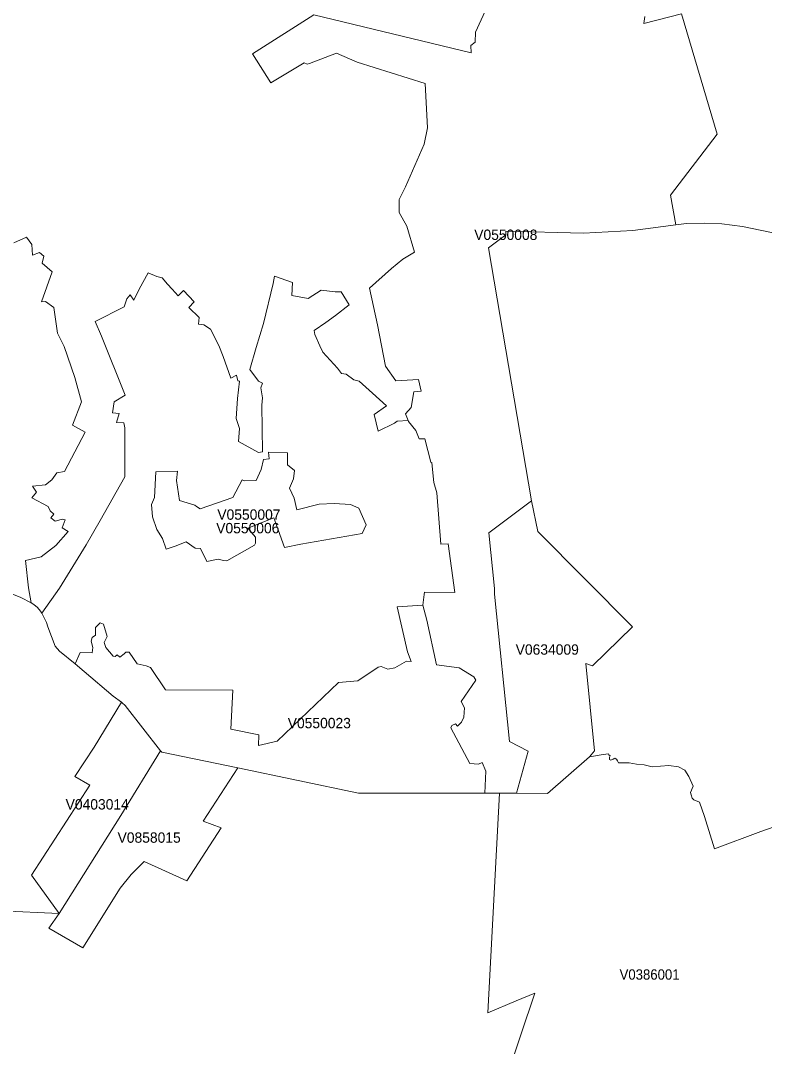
# Model space of a CAD drawing. Extents: x 369010 to 735936, y 6377141 to 6616555.
# Drawn here: x 433279 to 440462, y 6480546 to 6490450 of the extents above; entities that cross this region are included whole.
import ezdxf
from ezdxf.enums import TextEntityAlignment as Align

# ---------------------------------------------------------------- set-up
doc = ezdxf.new("R2010")
doc.units = 0
doc.header["$LTSCALE"] = 40
doc.layers.add('3', color=7, linetype='Continuous', lineweight=13)
doc.layers.add('4', color=7, linetype='Continuous')

msp = doc.modelspace()

# ---------------------------------------------------------------- linework, layer by layer
at = {"layer": '3'}
for points in [[(437780.59, 6490576.1), (437671.19, 6490336.45), (437667.22, 6490241.45), (437627.17, 6490208.52), (437631.14, 6490138.84), (436110.33, 6490505.93), (435519.31, 6490129.24), (435695.24, 6489847.06), (436018.97, 6490041.53), (436044.79, 6490029.28), (436069.94, 6490035.07), (436328.63, 6490133.05), (436530.21, 6490047.98), (437184.94, 6489841.43), (437207.95, 6489413.6), (437176.01, 6489256.87), (436994.78, 6488844.27), (436934.7, 6488720.8), (436933.54, 6488596.84), (437009.01, 6488465.27), (437082.5, 6488214.36), (436970.62, 6488144.68), (436859.07, 6488055.64), (436648.88, 6487866.31), (436726.33, 6487510.8), (436801.31, 6487112.11), (436901.77, 6486971.59), (437121.72, 6486985.16), (437148.04, 6486870.3), (437075.21, 6486863.85), (437049.56, 6486714.4), (436997.26, 6486653.66), (437022.09, 6486587.29), (437024.9, 6486579.51), (437095.74, 6486491.13), (437126.69, 6486411.86), (437181.47, 6486410.53), (437239.56, 6486184.95), (437250.48, 6486181.15), (437270.84, 6485991.15), (437297.98, 6485891.84), (437336.71, 6485394.34), (437409.04, 6485398.81), (437471.6, 6484929.27), (437180.64, 6484932.75), (437177.33, 6484908.75), (437162.93, 6484804.65), (437201.99, 6484662.48), (437294.84, 6484229.69), (437515.12, 6484200.56), (437655.47, 6484113.5), (437675.17, 6484080.24), (437534.82, 6483875.18), (437566.43, 6483813.28), (437557.99, 6483724.57), (437535.81, 6483675.75), (437498.74, 6483637.02), (437477.22, 6483661.18), (437444.62, 6483643.64), (437432.21, 6483620.14), (437617.74, 6483278.87), (437701.32, 6483271.09), (437736.73, 6483288.3), (437770, 6483202.9), (437760.4, 6482990.89), (437904.72, 6482990.72), (438066.75, 6482989.9), (438180.12, 6483395.88), (438001.21, 6483488.4), (437855.24, 6484912.56), (437855.24, 6484968.17), (437800.29, 6485502.91), (438213.22, 6485811.91), (437795.82, 6488254.74), (437964.3, 6488381.52), (437963.47, 6488414.95), (438713.7, 6488397.41), (439190.19, 6488422.9), (439607.1, 6488477.84), (439553.64, 6488763.34), (440006.29, 6489352.37), (439660.88, 6490514.87), (439298.43, 6490421.36), (439305.55, 6490489.05)], [(437022.09, 6486587.29), (436997.26, 6486653.66), (437049.56, 6486714.4), (437075.21, 6486863.85), (437148.04, 6486870.3), (437121.72, 6486985.16), (436901.77, 6486971.59), (436801.31, 6487112.11), (436726.33, 6487510.8), (436648.88, 6487866.31), (436859.07, 6488055.64), (436970.62, 6488144.68), (437082.5, 6488214.36), (437009.01, 6488465.27), (436933.54, 6488596.84), (436934.7, 6488720.8), (436994.78, 6488844.27), (437176.01, 6489256.87), (437207.95, 6489413.6), (437184.94, 6489841.43), (436530.21, 6490047.98), (436328.63, 6490133.05), (436069.94, 6490035.07), (436044.79, 6490029.28), (436018.97, 6490041.53), (435695.24, 6489847.06), (435519.31, 6490129.24), (436110.33, 6490505.93)], [(436110.33, 6490505.93), (437631.14, 6490138.84), (437627.17, 6490208.52), (437667.22, 6490241.45), (437671.19, 6490336.45), (437780.59, 6490576.1)], [(439305.55, 6490489.05), (439298.43, 6490421.36), (439660.88, 6490514.87), (440006.29, 6489352.37)], [(440006.29, 6489352.37), (439553.64, 6488763.34), (439607.1, 6488477.84), (439707.72, 6488491.25), (439879.51, 6488494.06), (440049.65, 6488488.6), (440248.92, 6488462.62), (440962.9, 6488312.51)], [(440962.9, 6488312.51), (440248.92, 6488462.62), (440049.65, 6488488.6), (439879.51, 6488494.06), (439707.72, 6488491.25), (439607.1, 6488477.84), (439190.19, 6488422.9), (438713.7, 6488397.41), (437963.47, 6488414.95), (437964.3, 6488381.52), (437795.82, 6488254.74), (438213.22, 6485811.91), (438273.3, 6485518.47), (439187.05, 6484598.1), (438802.25, 6484219.26), (438736.21, 6484243.26), (438820.29, 6483401.17), (438770.8, 6483343.25), (438905.85, 6483363.44), (438955.84, 6483369.89), (438959.64, 6483360.13), (438971.39, 6483352.68), (438966.1, 6483337.12), (438966.59, 6483315.61), (438977.85, 6483310.31), (438999.86, 6483319.42), (439015.42, 6483327.53), (439026.18, 6483322.56), (439034.29, 6483318.26), (439041.24, 6483301.71), (439050.84, 6483284.49), (439154.44, 6483285.16), (439227.43, 6483272.08), (439299.59, 6483264.47), (439377.38, 6483246.43), (439539.57, 6483258.51), (439633.24, 6483244.44), (439692.5, 6483211.67), (439732.38, 6483150.77), (439772.6, 6483059.08), (439746.95, 6482996.52), (439754.56, 6482973.35), (439764.82, 6482942.4), (439778.56, 6482927.83), (439833.5, 6482903.83), (439882.16, 6482766.3), (439978.98, 6482454.66), (440425.02, 6482620.16), (440885.78, 6482782.52)], [(433162.2, 6484926.96), (433280.21, 6484879.13), (433381, 6484828.98), (433357, 6484973.96), (433325.56, 6485237.11), (433477.32, 6485272.86), (433620.82, 6485380.93), (433737.33, 6485517.47), (433681.56, 6485553.72), (433709.53, 6485630.35), (433682.88, 6485635.48), (433669.97, 6485633), (433614.2, 6485615.45), (433570.67, 6485649.88), (433598.97, 6485685.46), (433563.88, 6485715.91), (433546.34, 6485756.79), (433386.96, 6485841.7), (433432.14, 6485897.97), (433393.08, 6485953.74), (433520.35, 6485966.65), (433582.58, 6486016.3), (433630.58, 6486082.5), (433703.24, 6486094.75), (433904.16, 6486475.25), (433780.03, 6486543.6), (433866.75, 6486769.51), (433801.71, 6487003.7), (433698.93, 6487302.27), (433636.04, 6487432.69), (433599.13, 6487680.11), (433521.35, 6487737.54), (433480.47, 6487735.06), (433583.91, 6488024.03), (433486.92, 6488106.12), (433505.13, 6488173.48), (433463.59, 6488210.56), (433393.41, 6488183.58), (433386.46, 6488288.84), (433337.8, 6488359.51), (433215, 6488302.91)], [(433215, 6488302.91), (433337.8, 6488359.51), (433386.46, 6488288.84), (433393.41, 6488183.58), (433463.59, 6488210.56), (433505.13, 6488173.48), (433486.92, 6488106.12), (433583.91, 6488024.03), (433480.47, 6487735.06), (433521.35, 6487737.54), (433599.13, 6487680.11), (433636.04, 6487432.69), (433698.93, 6487302.27), (433801.71, 6487003.7), (433866.75, 6486769.51), (433780.03, 6486543.6), (433904.16, 6486475.25), (433703.24, 6486094.75), (433630.58, 6486082.5), (433582.58, 6486016.3), (433520.35, 6485966.65), (433393.08, 6485953.74), (433432.14, 6485897.97)], [(433432.14, 6485897.97), (433386.96, 6485841.7), (433546.34, 6485756.79), (433563.88, 6485715.91), (433598.97, 6485685.46), (433570.67, 6485649.88), (433614.2, 6485615.45), (433669.97, 6485633), (433682.88, 6485635.48), (433709.53, 6485630.35), (433681.56, 6485553.72), (433737.33, 6485517.47), (433620.82, 6485380.93), (433477.32, 6485272.86), (433325.56, 6485237.11), (433357, 6484973.96), (433381, 6484828.98), (433382.32, 6484828.32), (433408.31, 6484812.1), (433442.4, 6484782.14), (433473.02, 6484747.38), (433482.95, 6484727.52), (433655.24, 6484968.83), (433911.44, 6485388.55), (434049.31, 6485624.72), (434287.3, 6486044.27), (434284.32, 6486517.78), (434276.54, 6486566.44), (434207.03, 6486567.76), (434231.86, 6486654.65), (434166.98, 6486661.77), (434183.36, 6486768.68), (434290.61, 6486832.57), (434061.06, 6487403.89), (434000.81, 6487543.41), (434279.02, 6487684.75), (434305.51, 6487762.7), (434338.11, 6487800.27), (434372.87, 6487748.8), (434425.83, 6487857.2), (434511.72, 6488012.78), (434594.31, 6487979.18), (434647.11, 6487966.6), (434696.76, 6487905.37), (434744.42, 6487855.71), (434801.19, 6487792.99), (434851.5, 6487844.46), (434954.61, 6487732.58), (434902.97, 6487677.8), (435004.76, 6487584.29), (434997.64, 6487517.92), (435048.62, 6487512.13), (435111.84, 6487469.59), (435194.1, 6487313.36), (435235.97, 6487204.95), (435308.79, 6486997.58), (435364.73, 6487024.88), (435375.65, 6486970.76), (435394.36, 6486966.79), (435373.83, 6486801.62), (435359.44, 6486606.66), (435394.36, 6486510.66), (435383.93, 6486384.71), (435577.24, 6486280.94), (435614.64, 6486284.92), (435609.18, 6486736.91), (435614.31, 6486807.58), (435598.26, 6486902.41), (435614.31, 6486947.59), (435577.07, 6486967.29), (435493.33, 6487079.5), (435554.07, 6487293.66), (435624.24, 6487524.04), (435718.91, 6487911.16), (435731.82, 6487980.84), (435906.26, 6487919.43), (435897.82, 6487796.13), (436056.54, 6487767.83), (436180, 6487846.12), (436318.2, 6487831.72), (436374.47, 6487829.73), (436450.6, 6487705.93), (436320.85, 6487602.66), (436227.83, 6487534.97), (436112.81, 6487458.67), (436119.93, 6487418.78), (436168.92, 6487309.05), (436197.22, 6487248.31), (436340.21, 6487092.58), (436376.95, 6487040.94), (436422.8, 6487036.47), (436497.44, 6486982.68), (436547.09, 6486969.77), (436676.68, 6486853.92), (436813.88, 6486729.96), (436693.56, 6486646.21), (436731.96, 6486485.67), (436888.03, 6486561.64), (436915.83, 6486582.33), (437022.09, 6486587.29)], [(435394.36, 6486966.79), (435375.65, 6486970.76), (435364.73, 6487024.88), (435308.79, 6486997.58), (435235.97, 6487204.95), (435194.1, 6487313.36), (435111.84, 6487469.59), (435048.62, 6487512.13), (434997.64, 6487517.92), (435004.76, 6487584.29), (434902.97, 6487677.8), (434954.61, 6487732.58), (434851.5, 6487844.46), (434801.19, 6487792.99), (434744.42, 6487855.71), (434696.76, 6487905.37), (434647.11, 6487966.6), (434594.31, 6487979.18), (434511.72, 6488012.78), (434425.83, 6487857.2), (434372.87, 6487748.8), (434338.11, 6487800.27), (434305.51, 6487762.7), (434279.02, 6487684.75), (434000.81, 6487543.41), (434061.06, 6487403.89), (434290.61, 6486832.57), (434183.36, 6486768.68), (434166.98, 6486661.77), (434231.86, 6486654.65), (434207.03, 6486567.76), (434276.54, 6486566.44), (434284.32, 6486517.78), (434287.3, 6486044.27), (434049.31, 6485624.72), (433911.44, 6485388.55), (433655.24, 6484968.83), (433482.95, 6484727.52)], [(433482.95, 6484727.52), (433528.13, 6484637.49), (433542.86, 6484595.78), (433612.71, 6484411.08), (433656.23, 6484362.26), (433805.85, 6484238.13), (433854.84, 6484349.84), (433971.85, 6484346.37), (433975.82, 6484397.84), (433962.08, 6484457.92), (433971.85, 6484492.51), (434001.81, 6484514.69), (434003.79, 6484591.64), (434048.81, 6484634.01), (434079.92, 6484622.43), (434115.67, 6484503.1), (434087.7, 6484445.67), (434101.94, 6484396.02), (434173.1, 6484314.43), (434191.97, 6484309.29), (434213.49, 6484326.01), (434236.82, 6484303.17), (434278.03, 6484337.1), (434295.24, 6484350.67), (434326.52, 6484350.67), (434404.81, 6484240.94), (434493.19, 6484221.41), (434532.41, 6484203.7), (434678.88, 6483989.21), (435329.81, 6483985.9), (435308.29, 6483607.72), (435580.22, 6483553.6), (435576.41, 6483451.16), (435755.49, 6483493.03), (436347.66, 6484058.89), (436535.01, 6484074.61), (436730.64, 6484206.35), (436761.25, 6484214.13), (436825.3, 6484189.3), (436892.66, 6484200.89), (437004.21, 6484264.61), (437051.22, 6484262.62), (437014.64, 6484356.63), (436915.17, 6484790.58), (437162.93, 6484804.65), (437177.33, 6484908.75), (437180.64, 6484932.75), (437471.6, 6484929.27), (437409.04, 6485398.81), (437336.71, 6485394.34), (437297.98, 6485891.84), (437270.84, 6485991.15), (437250.48, 6486181.15), (437239.56, 6486184.95), (437181.47, 6486410.53), (437126.69, 6486411.86), (437095.74, 6486491.13), (437024.9, 6486579.51), (437022.09, 6486587.29), (436915.83, 6486582.33), (436888.03, 6486561.64), (436731.96, 6486485.67), (436693.56, 6486646.21), (436813.88, 6486729.96), (436676.68, 6486853.92), (436547.09, 6486969.77), (436497.44, 6486982.68), (436422.8, 6487036.47), (436376.95, 6487040.94), (436340.21, 6487092.58), (436197.22, 6487248.31), (436168.92, 6487309.05), (436119.93, 6487418.78), (436112.81, 6487458.67), (436227.83, 6487534.97), (436320.85, 6487602.66), (436450.6, 6487705.93), (436374.47, 6487829.73), (436318.2, 6487831.72), (436180, 6487846.12), (436056.54, 6487767.83), (435897.82, 6487796.13), (435906.26, 6487919.43), (435731.82, 6487980.84), (435718.91, 6487911.16), (435624.24, 6487524.04), (435554.07, 6487293.66), (435493.33, 6487079.5), (435577.07, 6486967.29), (435614.31, 6486947.59), (435598.26, 6486902.41), (435614.31, 6486807.58), (435609.18, 6486736.91), (435614.64, 6486284.92), (435577.24, 6486280.94), (435383.93, 6486384.71), (435394.36, 6486510.66), (435359.44, 6486606.66), (435373.83, 6486801.62), (435394.36, 6486966.79)], [(433088.22, 6481856.03), (433652.59, 6481829.22), (433384.64, 6482198.62), (433947.52, 6483068.84), (433803.86, 6483152.42), (433990.05, 6483434.94), (434254.53, 6483868.23), (434172.94, 6483926.65), (433891.75, 6484166.8), (433805.85, 6484238.13), (433656.23, 6484362.26), (433612.71, 6484411.08), (433542.86, 6484595.78), (433528.13, 6484637.49), (433482.95, 6484727.52), (433473.02, 6484747.38), (433442.4, 6484782.14), (433408.31, 6484812.1), (433382.32, 6484828.32), (433381, 6484828.98), (433280.21, 6484879.13), (433162.2, 6484926.96)], [(440885.78, 6482782.52), (440425.02, 6482620.16), (439978.98, 6482454.66), (439882.16, 6482766.3), (439833.5, 6482903.83), (439778.56, 6482927.83), (439764.82, 6482942.4), (439754.56, 6482973.35), (439746.95, 6482996.52), (439772.6, 6483059.08), (439732.38, 6483150.77), (439692.5, 6483211.67), (439633.24, 6483244.44), (439539.57, 6483258.51), (439377.38, 6483246.43), (439299.59, 6483264.47), (439227.43, 6483272.08), (439154.44, 6483285.16), (439050.84, 6483284.49), (439041.24, 6483301.71), (439034.29, 6483318.26), (439026.18, 6483322.56), (439015.42, 6483327.53), (438999.86, 6483319.42), (438977.85, 6483310.31), (438966.59, 6483315.61), (438966.1, 6483337.12), (438971.39, 6483352.68), (438959.64, 6483360.13), (438955.84, 6483369.89), (438905.85, 6483363.44), (438770.8, 6483343.25), (438365.65, 6482989.23), (438066.75, 6482989.9), (437904.72, 6482990.72), (437791.52, 6480871.28), (438064.43, 6480985.15), (438244, 6481059.13), (437970.43, 6480244.85)], [(435376.15, 6483235.17), (435040.84, 6482720.46), (435215.61, 6482656.41), (434885.76, 6482145.66), (434473.33, 6482330.53), (434346.55, 6482204.25), (434240.96, 6482074.83), (433881.32, 6481498.37), (433550.97, 6481687.71), (433652.59, 6481829.22), (433088.22, 6481856.03)], [(437970.43, 6480244.85), (438244, 6481059.13), (438064.43, 6480985.15), (437791.52, 6480871.28), (437904.72, 6482990.72), (437760.4, 6482990.89), (436541.3, 6482992.21), (435376.15, 6483235.17)]]:
    msp.add_lwpolyline(points, dxfattribs=at)
for points in [[(434795.4, 6486100.05), (434586.37, 6486092.6), (434573.46, 6485843.68), (434544.16, 6485777.81), (434553.76, 6485660.14), (434593.81, 6485536.51), (434650.75, 6485450.44), (434684.34, 6485347), (434772.89, 6485375.8), (434879.64, 6485418.01), (434965.37, 6485357.43), (435015.85, 6485353.46), (435076.75, 6485225.86), (435188.63, 6485249.85), (435239.61, 6485236.28), (435269.24, 6485232.48), (435538.01, 6485384.41), (435548.77, 6485405.1), (435547.45, 6485463.19), (435473.3, 6485549.58), (435724.04, 6485648.06), (435735.13, 6485623.56), (435827.81, 6485363.39), (435983.72, 6485394.01), (436577.88, 6485496.79), (436616.6, 6485579.87), (436545.77, 6485741.73), (436463.35, 6485779.14), (436308.43, 6485787.91), (436160.64, 6485780.46), (435946.97, 6485725.18), (435920.82, 6485839.54), (435876.8, 6485934.38), (435913.54, 6486026.56), (435925.13, 6486105.18), (435857.27, 6486160.29), (435856.61, 6486218.88), (435857.93, 6486274.99), (435673.73, 6486281.61), (435679.52, 6486220.04), (435624.74, 6486211.6), (435602.06, 6486116.27), (435552.74, 6486009.68), (435439.7, 6486005.21), (435419.84, 6486014.15), (435329.48, 6485846), (435012.37, 6485735.61), (434976.29, 6485756.79), (434961.4, 6485770.36), (434814.26, 6485816.87), (434785.14, 6486009.19)], [(434795.4, 6486100.05), (434785.14, 6486009.19), (434814.26, 6485816.87), (434961.4, 6485770.36), (434976.29, 6485756.79), (435012.37, 6485735.61), (435329.48, 6485846), (435419.84, 6486014.15), (435439.7, 6486005.21), (435552.74, 6486009.68), (435602.06, 6486116.27), (435624.74, 6486211.6), (435679.52, 6486220.04), (435673.73, 6486281.61), (435857.93, 6486274.99), (435856.61, 6486218.88), (435857.27, 6486160.29), (435925.13, 6486105.18), (435913.54, 6486026.56), (435876.8, 6485934.38), (435920.82, 6485839.54), (435946.97, 6485725.18), (436160.64, 6485780.46), (436308.43, 6485787.91), (436463.35, 6485779.14), (436545.77, 6485741.73), (436616.6, 6485579.87), (436577.88, 6485496.79), (435983.72, 6485394.01), (435827.81, 6485363.39), (435735.13, 6485623.56), (435724.04, 6485648.06), (435473.3, 6485549.58), (435547.45, 6485463.19), (435548.77, 6485405.1), (435538.01, 6485384.41), (435269.24, 6485232.48), (435239.61, 6485236.28), (435188.63, 6485249.85), (435076.75, 6485225.86), (435015.85, 6485353.46), (434965.37, 6485357.43), (434879.64, 6485418.01), (434772.89, 6485375.8), (434684.34, 6485347), (434650.75, 6485450.44), (434593.81, 6485536.51), (434553.76, 6485660.14), (434544.16, 6485777.81), (434573.46, 6485843.68), (434586.37, 6486092.6)], [(438213.22, 6485811.91), (437800.29, 6485502.91), (437855.24, 6484968.17), (437855.24, 6484912.56), (438001.21, 6483488.4), (438180.12, 6483395.88), (438066.75, 6482989.9), (438365.65, 6482989.23), (438770.8, 6483343.25), (438820.29, 6483401.17), (438736.21, 6484243.26), (438802.25, 6484219.26), (439187.05, 6484598.1), (438273.3, 6485518.47)], [(437162.93, 6484804.65), (436915.17, 6484790.58), (437014.64, 6484356.63), (437051.22, 6484262.62), (437004.21, 6484264.61), (436892.66, 6484200.89), (436825.3, 6484189.3), (436761.25, 6484214.13), (436730.64, 6484206.35), (436535.01, 6484074.61), (436347.66, 6484058.89), (435755.49, 6483493.03), (435576.41, 6483451.16), (435580.22, 6483553.6), (435308.29, 6483607.72), (435329.81, 6483985.9), (434678.88, 6483989.21), (434532.41, 6484203.7), (434493.19, 6484221.41), (434404.81, 6484240.94), (434326.52, 6484350.67), (434295.24, 6484350.67), (434278.03, 6484337.1), (434236.82, 6484303.17), (434213.49, 6484326.01), (434191.97, 6484309.29), (434173.1, 6484314.43), (434101.94, 6484396.02), (434087.7, 6484445.67), (434115.67, 6484503.1), (434079.92, 6484622.43), (434048.81, 6484634.01), (434003.79, 6484591.64), (434001.81, 6484514.69), (433971.85, 6484492.51), (433962.08, 6484457.92), (433975.82, 6484397.84), (433971.85, 6484346.37), (433854.84, 6484349.84), (433805.85, 6484238.13), (433891.75, 6484166.8), (434172.94, 6483926.65), (434254.53, 6483868.23), (434260.32, 6483864.09), (434288.96, 6483836.62), (434630.22, 6483400.51), (434642.31, 6483388.1), (435376.15, 6483235.17), (436541.3, 6482992.21), (437760.4, 6482990.89), (437770, 6483202.9), (437736.73, 6483288.3), (437701.32, 6483271.09), (437617.74, 6483278.87), (437432.21, 6483620.14), (437444.62, 6483643.64), (437477.22, 6483661.18), (437498.74, 6483637.02), (437535.81, 6483675.75), (437557.99, 6483724.57), (437566.43, 6483813.28), (437534.82, 6483875.18), (437675.17, 6484080.24), (437655.47, 6484113.5), (437515.12, 6484200.56), (437294.84, 6484229.69), (437201.99, 6484662.48)], [(434254.53, 6483868.23), (433990.05, 6483434.94), (433803.86, 6483152.42), (433947.52, 6483068.84), (433384.64, 6482198.62), (433652.59, 6481829.22), (434245.92, 6482775.73), (434630.22, 6483400.51), (434288.96, 6483836.62), (434260.32, 6483864.09)], [(434630.22, 6483400.51), (434245.92, 6482775.73), (433652.59, 6481829.22), (433550.97, 6481687.71), (433881.32, 6481498.37), (434240.96, 6482074.83), (434346.55, 6482204.25), (434473.33, 6482330.53), (434885.76, 6482145.66), (435215.61, 6482656.41), (435040.84, 6482720.46), (435376.15, 6483235.17), (434642.31, 6483388.1)]]:
    msp.add_lwpolyline(points, close=True, dxfattribs=at)

# ---------------------------------------------------------------- texts
at = {"layer": '4'}
for s, p in [('V0550008', (437964.3, 6488331.52)), ('V0550007', (435483.93, 6485630.47)), ('V0550006', (435473.3, 6485499.58)), ('V0634009', (438364.56, 6484327.68)), ('V0550023', (436163.6, 6483617.7)), ('V0403014', (434019.34, 6482833.04)), ('V0858015', (434520.79, 6482512.36))]:
    msp.add_text(s, height=100, dxfattribs=at).set_placement(p, align=Align.CENTER)
at = {"layer": '4', "width": 0.95}
msp.add_text('V0386001', height=100, dxfattribs=at).set_placement((439352.42, 6481190.4), align=Align.CENTER)

doc.saveas('drawing.dxf')
